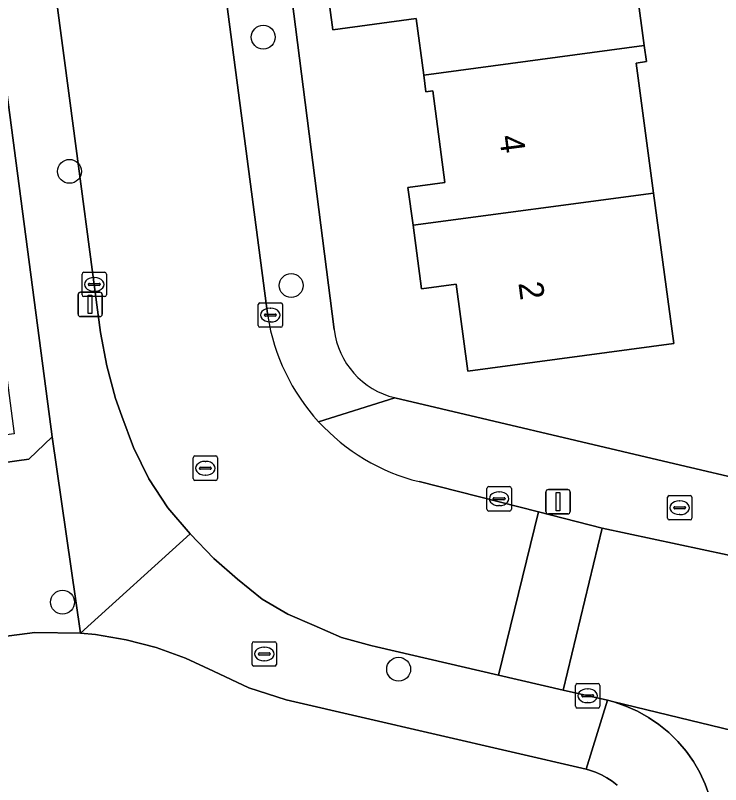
# Model space of a CAD drawing. Extents: x 161084 to 161928, y 385354 to 386522.
# Drawn here: x 161256.68 to 161285.53, y 385868.26 to 385899.73 of the extents above; entities that cross this region are included whole.
import ezdxf

# ---------------------------------------------------------------- set-up
doc = ezdxf.new("R2010")
doc.units = 0
for name, color, linetype in [('IMGEO_Boom', 7, 'Continuous'), ('IMGEO_Brandkraan', 7, 'Continuous'), ('IMGEO_Erf', 7, 'Continuous'), ('IMGEO_Kolk', 7, 'Continuous'), ('IMGEO_Lichtmast', 7, 'Continuous'), ('IMGEO_Pand', 7, 'Continuous'), ('IMGEO_Pand_nummerreeks', 7, 'Continuous'), ('IMGEO_Rijbaan_lokaal_open', 7, 'Continuous'), ('IMGEO_Rioolput', 7, 'Continuous'), ('IMGEO_Voetpad_open', 7, 'Continuous')]:
    doc.layers.add(name, color=color, linetype=linetype)

msp = doc.modelspace()

# ---------------------------------------------------------------- linework, layer by layer
at = {"layer": 'IMGEO_Boom'}
for centre in [(161266.822, 385898.836), (161258.895, 385893.347), (161267.962, 385888.678), (161258.609, 385875.726), (161272.36, 385872.981)]:
    msp.add_circle(centre, 0.489, dxfattribs=at)
at = {"layer": 'IMGEO_Brandkraan'}
for p, q in [((161283.434, 385880.089), (161284.286, 385880.089)), ((161283.359, 385879.163), (161283.359, 385880.015)), ((161283.847, 385879.869), (161283.872, 385879.869)), ((161284.36, 385880.015), (161284.36, 385879.163)), ((161283.618, 385879.583), (161283.618, 385879.595)), ((161284.056, 385879.546), (161283.658, 385879.546)), ((161283.661, 385879.632), (161284.059, 385879.632)), ((161284.102, 385879.595), (161284.102, 385879.583)), ((161283.87, 385879.309), (161283.845, 385879.309)), ((161284.286, 385879.089), (161283.434, 385879.089)), ((161266.437, 385874.108), (161267.289, 385874.108)), ((161266.362, 385873.182), (161266.362, 385874.034)), ((161266.85, 385873.888), (161266.875, 385873.888)), ((161267.363, 385874.034), (161267.363, 385873.182)), ((161266.621, 385873.602), (161266.621, 385873.614)), ((161267.059, 385873.565), (161266.661, 385873.565)), ((161266.664, 385873.651), (161267.062, 385873.651)), ((161267.105, 385873.614), (161267.105, 385873.602)), ((161266.873, 385873.328), (161266.848, 385873.328)), ((161267.289, 385873.108), (161266.437, 385873.108))]:
    msp.add_line(p, q, dxfattribs=at)
for points in [[(161283.434, 385880.089), (161284.286, 385880.089)], [(161283.359, 385879.163), (161283.359, 385880.015)], [(161284.36, 385880.015), (161284.36, 385879.163)], [(161284.286, 385879.089), (161283.434, 385879.089)], [(161266.437, 385874.108), (161267.289, 385874.108)], [(161266.362, 385873.182), (161266.362, 385874.034)], [(161267.363, 385874.034), (161267.363, 385873.182)], [(161267.289, 385873.108), (161266.437, 385873.108)]]:
    msp.add_lwpolyline(points, dxfattribs=at)
for centre, radius, start, end in [((161283.436, 385880.013), 0.0765, 91.552, 178.448), ((161283.436, 385880.013), 0.0765, 91.552, 178.448), ((161284.284, 385880.013), 0.0765, 1.552, 88.448), ((161284.284, 385880.013), 0.0765, 1.552, 88.448), ((161283.658, 385879.592), 0.0403, 85.8775, 175.7526), ((161283.655, 385879.582), 0.0366, 178.938, 274.7102), ((161284.059, 385879.589), 0.043, 264.8664, 352.4533), ((161284.063, 385879.594), 0.0386, 1.7309, 96.639), ((161283.436, 385879.165), 0.0765, 181.552, 268.448), ((161283.436, 385879.165), 0.0765, 181.552, 268.448), ((161284.284, 385879.165), 0.0765, 271.552, 358.448), ((161284.284, 385879.165), 0.0765, 271.552, 358.448), ((161266.439, 385874.032), 0.0765, 91.552, 178.448), ((161266.439, 385874.032), 0.0765, 91.552, 178.448), ((161267.287, 385874.032), 0.0765, 1.552, 88.448), ((161267.287, 385874.032), 0.0765, 1.552, 88.448), ((161266.661, 385873.611), 0.0403, 85.8775, 175.7526), ((161266.658, 385873.601), 0.0366, 178.938, 274.7102), ((161267.062, 385873.608), 0.043, 264.8664, 352.4533), ((161267.066, 385873.613), 0.0386, 1.7309, 96.639), ((161266.439, 385873.184), 0.0765, 181.552, 268.448), ((161266.439, 385873.184), 0.0765, 181.552, 268.448), ((161267.287, 385873.184), 0.0765, 271.552, 358.448), ((161267.287, 385873.184), 0.0765, 271.552, 358.448)]:
    msp.add_arc(centre, radius, start, end, dxfattribs=at)
for centre, major_axis, ratio, start_param, end_param in [((161283.846, 385879.589), (-0.387, 0.002), 0.722429, 4.712389, 7.853982), ((161283.871, 385879.589), (-0.39, 0.002), 0.717154, 1.570796, 4.712389), ((161266.849, 385873.608), (-0.387, 0.002), 0.722429, 4.712389, 7.853982), ((161266.874, 385873.608), (-0.39, 0.002), 0.717154, 1.570796, 4.712389)]:
    msp.add_ellipse(centre, major_axis=major_axis, ratio=ratio, start_param=start_param, end_param=end_param, dxfattribs=at)
at = {"layer": 'IMGEO_Erf'}
for points in [[(161263.568, 385935.025), (161269.725, 385886.874)], [(161251.473, 385923.178), (161252.265, 385917.163), (161253.06, 385911.127), (161253.503, 385907.767), (161249.93, 385907.296), (161250.277, 385904.663), (161250.648, 385901.841), (161254.026, 385902.286), (161254.447, 385899.092), (161254.88, 385895.806), (161251.491, 385895.36), (161251.852, 385892.619), (161252.21, 385889.908), (161255.605, 385890.356), (161256.625, 385882.613), (161248.682, 385881.566), (161248.892, 385880.415), (161257.232, 385881.574), (161258.188, 385882.488), (161252.002, 385929.347)], [(161281.832, 385902.791), (161282.409, 385898.493), (161282.497, 385897.835), (161282.074, 385897.778), (161282.788, 385892.461), (161283.614, 385886.31), (161275.189, 385885.178), (161274.711, 385888.738), (161273.298, 385888.549), (161272.95, 385891.14), (161272.742, 385892.689), (161274.256, 385892.892), (161273.753, 385896.64), (161273.478, 385896.603), (161273.387, 385897.282), (161273.076, 385899.597), (161269.664, 385899.139), (161269.173, 385902.799)], [(161272.207, 385884.09), (161283.433, 385881.441), (161287.155, 385880.563), (161286.845, 385886.525)], [(161281.298, 385868.235), (161281.097, 385868.398), (161280.882, 385868.542), (161280.655, 385868.667), (161280.417, 385868.771), (161280.172, 385868.853), (161280.03, 385868.89), (161267.756, 385871.733), (161266.234, 385872.223), (161264.784, 385872.899), (161263.633, 385873.435), (161262.438, 385873.867), (161261.21, 385874.19), (161259.958, 385874.402), (161259.346, 385874.464), (161257.475, 385874.49), (161236.064, 385871.703)]]:
    msp.add_lwpolyline(points, dxfattribs=at)
msp.add_arc((161272.949, 385887.25), 3.245, 186.6451, 256.7903, dxfattribs=at)
at = {"layer": 'IMGEO_Kolk'}
for p, q in [((161259.48, 385889.223), (161260.332, 385889.223)), ((161259.405, 385888.297), (161259.405, 385889.149)), ((161259.893, 385889.003), (161259.918, 385889.003)), ((161260.406, 385889.149), (161260.406, 385888.297)), ((161259.664, 385888.717), (161259.664, 385888.729)), ((161260.102, 385888.68), (161259.704, 385888.68)), ((161259.707, 385888.766), (161260.105, 385888.766)), ((161260.148, 385888.729), (161260.148, 385888.717)), ((161259.916, 385888.443), (161259.891, 385888.443)), ((161260.332, 385888.223), (161259.48, 385888.223)), ((161266.687, 385887.969), (161267.539, 385887.969)), ((161266.612, 385887.043), (161266.612, 385887.895)), ((161267.1, 385887.749), (161267.125, 385887.749)), ((161267.613, 385887.895), (161267.613, 385887.043)), ((161266.871, 385887.463), (161266.871, 385887.475)), ((161267.309, 385887.426), (161266.911, 385887.426)), ((161266.914, 385887.512), (161267.312, 385887.512)), ((161267.355, 385887.475), (161267.355, 385887.463)), ((161267.123, 385887.189), (161267.098, 385887.189)), ((161267.539, 385886.969), (161266.687, 385886.969)), ((161275.972, 385879.529), (161275.972, 385880.381)), ((161276.047, 385880.455), (161276.899, 385880.455)), ((161276.973, 385880.381), (161276.973, 385879.529)), ((161276.46, 385880.235), (161276.485, 385880.235)), ((161276.231, 385879.949), (161276.231, 385879.961)), ((161276.669, 385879.912), (161276.271, 385879.912)), ((161276.274, 385879.998), (161276.672, 385879.998)), ((161276.715, 385879.961), (161276.715, 385879.949)), ((161276.899, 385879.455), (161276.047, 385879.455)), ((161276.483, 385879.675), (161276.458, 385879.675)), ((161279.596, 385871.471), (161279.596, 385872.323)), ((161279.671, 385872.397), (161280.523, 385872.397)), ((161280.597, 385872.323), (161280.597, 385871.471)), ((161279.855, 385871.891), (161279.855, 385871.903)), ((161279.898, 385871.94), (161280.296, 385871.94)), ((161280.084, 385872.177), (161280.109, 385872.177)), ((161280.339, 385871.903), (161280.339, 385871.891)), ((161280.293, 385871.854), (161279.895, 385871.854)), ((161280.107, 385871.617), (161280.082, 385871.617)), ((161280.523, 385871.397), (161279.671, 385871.397))]:
    msp.add_line(p, q, dxfattribs=at)
for points in [[(161259.48, 385889.223), (161260.332, 385889.223)], [(161259.405, 385888.297), (161259.405, 385889.149)], [(161260.406, 385889.149), (161260.406, 385888.297)], [(161260.332, 385888.223), (161259.48, 385888.223)], [(161266.687, 385887.969), (161267.539, 385887.969)], [(161266.612, 385887.043), (161266.612, 385887.895)], [(161267.613, 385887.895), (161267.613, 385887.043)], [(161267.539, 385886.969), (161266.687, 385886.969)], [(161275.972, 385879.529), (161275.972, 385880.381)], [(161276.047, 385880.455), (161276.899, 385880.455)], [(161276.973, 385880.381), (161276.973, 385879.529)], [(161276.899, 385879.455), (161276.047, 385879.455)], [(161279.596, 385871.471), (161279.596, 385872.323)], [(161279.671, 385872.397), (161280.523, 385872.397)], [(161280.597, 385872.323), (161280.597, 385871.471)], [(161280.523, 385871.397), (161279.671, 385871.397)]]:
    msp.add_lwpolyline(points, dxfattribs=at)
for centre, radius, start, end in [((161259.482, 385889.147), 0.0765, 91.552, 178.448), ((161259.482, 385889.147), 0.0765, 91.552, 178.448), ((161260.33, 385889.147), 0.0765, 1.552, 88.448), ((161260.33, 385889.147), 0.0765, 1.552, 88.448), ((161259.704, 385888.726), 0.0403, 85.8775, 175.7526), ((161259.701, 385888.716), 0.0366, 178.938, 274.7102), ((161260.105, 385888.723), 0.043, 264.8664, 352.4533), ((161260.109, 385888.728), 0.0386, 1.7309, 96.639), ((161259.482, 385888.299), 0.0765, 181.552, 268.448), ((161259.482, 385888.299), 0.0765, 181.552, 268.448), ((161260.33, 385888.299), 0.0765, 271.552, 358.448), ((161260.33, 385888.299), 0.0765, 271.552, 358.448), ((161266.689, 385887.893), 0.0765, 91.552, 178.448), ((161266.689, 385887.893), 0.0765, 91.552, 178.448), ((161267.537, 385887.893), 0.0765, 1.552, 88.448), ((161267.537, 385887.893), 0.0765, 1.552, 88.448), ((161266.911, 385887.472), 0.0403, 85.8775, 175.7526), ((161266.908, 385887.462), 0.0366, 178.938, 274.7102), ((161267.312, 385887.469), 0.043, 264.8664, 352.4533), ((161267.316, 385887.474), 0.0386, 1.7309, 96.639), ((161266.689, 385887.045), 0.0765, 181.552, 268.448), ((161266.689, 385887.045), 0.0765, 181.552, 268.448), ((161267.537, 385887.045), 0.0765, 271.552, 358.448), ((161267.537, 385887.045), 0.0765, 271.552, 358.448), ((161276.049, 385880.379), 0.0765, 91.552, 178.448), ((161276.049, 385880.379), 0.0765, 91.552, 178.448), ((161276.897, 385880.379), 0.0765, 1.552, 88.448), ((161276.897, 385880.379), 0.0765, 1.552, 88.448), ((161276.271, 385879.958), 0.0403, 85.8775, 175.7526), ((161276.268, 385879.948), 0.0366, 178.938, 274.7102), ((161276.672, 385879.955), 0.043, 264.8664, 352.4533), ((161276.676, 385879.96), 0.0386, 1.7309, 96.639), ((161276.049, 385879.531), 0.0765, 181.552, 268.448), ((161276.049, 385879.531), 0.0765, 181.552, 268.448), ((161276.897, 385879.531), 0.0765, 271.552, 358.448), ((161276.897, 385879.531), 0.0765, 271.552, 358.448), ((161279.673, 385872.321), 0.0765, 91.552, 178.448), ((161279.673, 385872.321), 0.0765, 91.552, 178.448), ((161280.521, 385872.321), 0.0765, 1.552, 88.448), ((161280.521, 385872.321), 0.0765, 1.552, 88.448), ((161279.895, 385871.9), 0.0403, 85.8775, 175.7526), ((161279.892, 385871.89), 0.0366, 178.938, 274.7102), ((161280.296, 385871.897), 0.043, 264.8664, 352.4533), ((161280.3, 385871.902), 0.0386, 1.7309, 96.639), ((161279.673, 385871.473), 0.0765, 181.552, 268.448), ((161279.673, 385871.473), 0.0765, 181.552, 268.448), ((161280.521, 385871.473), 0.0765, 271.552, 358.448), ((161280.521, 385871.473), 0.0765, 271.552, 358.448)]:
    msp.add_arc(centre, radius, start, end, dxfattribs=at)
for centre, major_axis, ratio, start_param, end_param in [((161259.892, 385888.723), (-0.387, 0.002), 0.722429, 4.712389, 7.853982), ((161259.917, 385888.723), (-0.39, 0.002), 0.717154, 1.570796, 4.712389), ((161267.099, 385887.469), (-0.387, 0.002), 0.722429, 4.712389, 7.853982), ((161267.124, 385887.469), (-0.39, 0.002), 0.717154, 1.570796, 4.712389), ((161276.459, 385879.955), (-0.387, 0.002), 0.722429, 4.712389, 7.853982), ((161276.484, 385879.955), (-0.39, 0.002), 0.717154, 1.570796, 4.712389), ((161280.083, 385871.897), (-0.387, 0.002), 0.722429, 4.712389, 7.853982), ((161280.108, 385871.897), (-0.39, 0.002), 0.717154, 1.570796, 4.712389)]:
    msp.add_ellipse(centre, major_axis=major_axis, ratio=ratio, start_param=start_param, end_param=end_param, dxfattribs=at)
at = {"layer": 'IMGEO_Lichtmast'}
for p, q in [((161259.243, 385887.504), (161259.243, 385888.304)), ((161259.243, 385888.304), (161259.243, 385887.504)), ((161259.343, 385888.404), (161260.133, 385888.404)), ((161260.133, 385888.404), (161259.343, 385888.404)), ((161260.233, 385888.304), (161260.233, 385887.504)), ((161260.233, 385887.504), (161260.233, 385888.304)), ((161260.133, 385887.404), (161259.343, 385887.404)), ((161259.343, 385887.404), (161260.133, 385887.404)), ((161278.387, 385879.433), (161278.387, 385880.233)), ((161278.387, 385880.233), (161278.387, 385879.433)), ((161278.487, 385880.333), (161279.277, 385880.333)), ((161279.277, 385880.333), (161278.487, 385880.333)), ((161279.377, 385880.233), (161279.377, 385879.433)), ((161279.377, 385879.433), (161279.377, 385880.233)), ((161279.277, 385879.333), (161278.487, 385879.333)), ((161278.487, 385879.333), (161279.277, 385879.333))]:
    msp.add_line(p, q, dxfattribs=at)
for points in [[(161259.663, 385888.279), (161259.813, 385888.279), (161259.813, 385887.529), (161259.663, 385887.529), (161259.663, 385888.279)], [(161278.807, 385880.208), (161278.957, 385880.208), (161278.957, 385879.458), (161278.807, 385879.458), (161278.807, 385880.208)]]:
    msp.add_lwpolyline(points, dxfattribs=at)
for centre, start, end in [((161259.343, 385888.304), 90, 180), ((161259.343, 385888.304), 90, 180), ((161260.133, 385888.304), 0, 90), ((161260.133, 385888.304), 360, 90), ((161259.343, 385887.504), 180, 270), ((161259.343, 385887.504), 180, 270), ((161260.133, 385887.504), 270, 0), ((161260.133, 385887.504), 270, 0), ((161278.487, 385880.233), 90, 180), ((161278.487, 385880.233), 90, 180), ((161279.277, 385880.233), 0, 90), ((161279.277, 385880.233), 360, 90), ((161278.487, 385879.433), 180, 270), ((161278.487, 385879.433), 180, 270), ((161279.277, 385879.433), 270, 0), ((161279.277, 385879.433), 270, 0)]:
    msp.add_arc(centre, 0.1, start, end, dxfattribs=at)
at = {"layer": 'IMGEO_Pand'}
for points in [[(161282.409, 385898.493), (161281.832, 385902.791), (161281.607, 385904.468), (161269.173, 385902.799), (161269.664, 385899.139), (161273.076, 385899.597), (161273.387, 385897.282)], [(161282.788, 385892.461), (161282.074, 385897.778), (161282.497, 385897.835), (161282.409, 385898.493), (161273.387, 385897.282), (161273.478, 385896.603), (161273.753, 385896.64), (161274.256, 385892.892), (161272.742, 385892.689), (161272.95, 385891.14)], [(161272.95, 385891.14), (161273.298, 385888.549), (161274.711, 385888.738), (161275.189, 385885.178), (161283.614, 385886.31), (161282.788, 385892.461)]]:
    msp.add_lwpolyline(points, close=True, dxfattribs=at)
at = {"layer": 'IMGEO_Rijbaan_lokaal_open'}
for points in [[(161248.067, 385978.597), (161256.871, 385911.557), (161257.309, 385908.263), (161258.033, 385902.817), (161258.922, 385896.131), (161260.168, 385886.756), (161260.415, 385885.391), (161260.782, 385884.053), (161261.033, 385883.337), (161261.516, 385882.059), (161262.143, 385880.777), (161262.923, 385879.579), (161263.827, 385878.528), (161264.804, 385877.517), (161265.77, 385876.664), (161266.781, 385875.85), (161267.827, 385875.24), (161268.907, 385874.769), (161270.024, 385874.279), (161271.217, 385873.952), (161271.458, 385873.896), (161276.452, 385872.742), (161278.079, 385879.424), (161273.199, 385880.655)], [(161267.007, 385887.426), (161263.934, 385910.799), (161262.973, 385917.539), (161260.642, 385935.92)], [(161236.064, 385871.703), (161257.475, 385874.49), (161259.346, 385874.464), (161258.188, 385882.488), (161257.232, 385881.574), (161248.892, 385880.415)], [(161299.018, 385867.307), (161298.896, 385867.349), (161281.16, 385871.644), (161281.652, 385871.476), (161282.128, 385871.265), (161282.583, 385871.013), (161283.013, 385870.72), (161283.416, 385870.391), (161283.787, 385870.026), (161284.125, 385869.63), (161284.425, 385869.206), (161284.687, 385868.756), (161284.908, 385868.285), (161285.085, 385867.796), (161285.218, 385867.293), (161285.306, 385866.78), (161285.347, 385866.261), (161285.342, 385865.741), (161285.291, 385865.223), (161285.193, 385864.712), (161281.693, 385849.708), (161281.275, 385847.826)]]:
    msp.add_lwpolyline(points, dxfattribs=at)
for points in [[(161280.685, 385878.758), (161278.079, 385879.424), (161276.452, 385872.742), (161279.098, 385872.13)], [(161300.329, 385874.229), (161297.138, 385874.964), (161286.824, 385877.442), (161280.685, 385878.758), (161279.098, 385872.13), (161280.909, 385871.711), (161281.16, 385871.644), (161298.896, 385867.349), (161299.018, 385867.307), (161300.869, 385866.835), (161305.945, 385865.616), (161307.604, 385872.468)]]:
    msp.add_lwpolyline(points, close=True, dxfattribs=at)
for centre, radius, start, end in [((161275.226, 385888.722), 8.321, 188.9628, 222.4236), ((161275.218, 385888.718), 8.312, 222.4397, 255.9404)]:
    msp.add_arc(centre, radius, start, end, dxfattribs=at)
at = {"layer": 'IMGEO_Rioolput'}
for p, q in [((161264.027, 385881.705), (161264.879, 385881.705)), ((161263.952, 385880.779), (161263.952, 385881.631)), ((161264.44, 385881.485), (161264.465, 385881.485)), ((161264.953, 385881.631), (161264.953, 385880.779)), ((161264.211, 385881.199), (161264.211, 385881.211)), ((161264.649, 385881.162), (161264.251, 385881.162)), ((161264.254, 385881.248), (161264.652, 385881.248)), ((161264.695, 385881.211), (161264.695, 385881.199)), ((161264.879, 385880.705), (161264.027, 385880.705)), ((161264.463, 385880.925), (161264.438, 385880.925))]:
    msp.add_line(p, q, dxfattribs=at)
for points in [[(161264.027, 385881.705), (161264.879, 385881.705)], [(161263.952, 385880.779), (161263.952, 385881.631)], [(161264.953, 385881.631), (161264.953, 385880.779)], [(161264.879, 385880.705), (161264.027, 385880.705)]]:
    msp.add_lwpolyline(points, dxfattribs=at)
for centre, radius, start, end in [((161264.029, 385881.629), 0.0765, 91.552, 178.448), ((161264.029, 385881.629), 0.0765, 91.552, 178.448), ((161264.877, 385881.629), 0.0765, 1.552, 88.448), ((161264.877, 385881.629), 0.0765, 1.552, 88.448), ((161264.251, 385881.208), 0.0403, 85.8775, 175.7526), ((161264.248, 385881.198), 0.0366, 178.938, 274.7102), ((161264.652, 385881.205), 0.043, 264.8664, 352.4533), ((161264.656, 385881.21), 0.0386, 1.7309, 96.639), ((161264.029, 385880.781), 0.0765, 181.552, 268.448), ((161264.029, 385880.781), 0.0765, 181.552, 268.448), ((161264.877, 385880.781), 0.0765, 271.552, 358.448), ((161264.877, 385880.781), 0.0765, 271.552, 358.448)]:
    msp.add_arc(centre, radius, start, end, dxfattribs=at)
for centre, major_axis, ratio, start_param, end_param in [((161264.439, 385881.205), (-0.387, 0.002), 0.722429, 4.712389, 7.853982), ((161264.464, 385881.205), (-0.39, 0.002), 0.717154, 1.570796, 4.712389)]:
    msp.add_ellipse(centre, major_axis=major_axis, ratio=ratio, start_param=start_param, end_param=end_param, dxfattribs=at)
at = {"layer": 'IMGEO_Voetpad_open'}
for points in [[(161269.725, 385886.874), (161263.568, 385935.025), (161263.263, 385937.353), (161258.189, 385975.824), (161258.145, 385976.159), (161257.909, 385977.952), (161255.001, 386000), (161252.413, 386019.447)], [(161260.642, 385935.92), (161262.973, 385917.539), (161263.934, 385910.799), (161267.007, 385887.426)], [(161269.084, 385883.109), (161272.207, 385884.09)], [(161298.584, 385877.782), (161287.155, 385880.563), (161283.433, 385881.441), (161272.207, 385884.09), (161269.084, 385883.109)], [(161273.199, 385880.655), (161278.079, 385879.424), (161280.685, 385878.758), (161286.824, 385877.442), (161297.138, 385874.964), (161300.329, 385874.229), (161307.604, 385872.468), (161310.394, 385871.792), (161318.268, 385869.886), (161322.316, 385868.902)], [(161285.085, 385867.796), (161284.908, 385868.285), (161284.687, 385868.756), (161284.425, 385869.206), (161284.125, 385869.63), (161283.787, 385870.026), (161283.416, 385870.391), (161283.013, 385870.72), (161282.583, 385871.013), (161282.128, 385871.265), (161281.652, 385871.476), (161281.16, 385871.644), (161280.909, 385871.711), (161280.03, 385868.89), (161280.172, 385868.853), (161280.417, 385868.771), (161280.655, 385868.667), (161280.882, 385868.542), (161281.097, 385868.398), (161281.298, 385868.235)]]:
    msp.add_lwpolyline(points, dxfattribs=at)
for points in [[(161248.067, 385978.597), (161247.586, 385978.531), (161246.916, 385983.683), (161245.002, 385983.429), (161245.764, 385976.325), (161247.222, 385965.488), (161249.386, 385949.483), (161252.002, 385929.347), (161258.188, 385882.488), (161259.346, 385874.464), (161263.827, 385878.528), (161262.923, 385879.579), (161262.143, 385880.777), (161261.516, 385882.059), (161261.033, 385883.337), (161260.782, 385884.053), (161260.415, 385885.391), (161260.168, 385886.756), (161258.922, 385896.131), (161258.033, 385902.817), (161257.309, 385908.263), (161256.871, 385911.557)], [(161271.458, 385873.896), (161271.217, 385873.952), (161270.024, 385874.279), (161268.907, 385874.769), (161267.827, 385875.24), (161266.781, 385875.85), (161265.77, 385876.664), (161264.804, 385877.517), (161263.827, 385878.528), (161259.346, 385874.464), (161259.958, 385874.402), (161261.21, 385874.19), (161262.438, 385873.867), (161263.633, 385873.435), (161264.784, 385872.899), (161266.234, 385872.223), (161267.756, 385871.733), (161280.03, 385868.89), (161280.909, 385871.711), (161279.098, 385872.13), (161276.452, 385872.742)]]:
    msp.add_lwpolyline(points, close=True, dxfattribs=at)
for centre, radius, start, end in [((161275.226, 385888.722), 8.321, 188.9628, 222.4236), ((161272.949, 385887.25), 3.245, 186.6451, 256.7903), ((161275.218, 385888.718), 8.312, 222.4397, 255.9404)]:
    msp.add_arc(centre, radius, start, end, dxfattribs=at)

# ---------------------------------------------------------------- texts
at = {"layer": 'IMGEO_Pand_nummerreeks'}
for s, p in [('4', (161276.473, 385894.782)), ('2', (161277.259, 385888.781))]:
    msp.add_text(s, height=1, rotation=277.4538, dxfattribs=at).set_placement(p)

doc.saveas('drawing.dxf')
